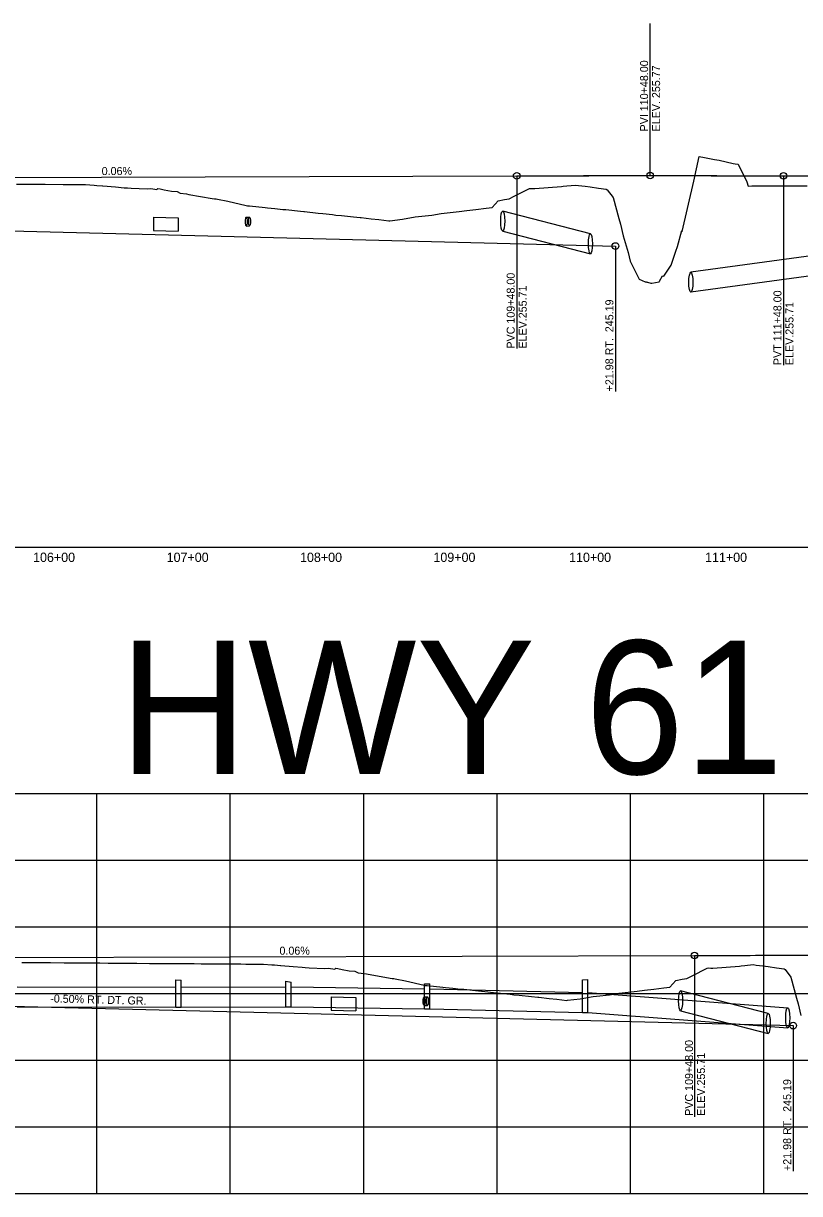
# Model space of a CAD drawing. Extents: x 1930770 to 1938778, y 596900 to 600561.
# Drawn here: x 1932838 to 1933419, y 598575 to 599452 of the extents above; entities that cross this region are included whole.
import ezdxf

# ---------------------------------------------------------------- set-up
doc = ezdxf.new("R2010")
doc.units = 0
for name, color, linetype in [('R_Concrete Hidden', 7, 'Continuous'), ('S_CROSS_DRAIN_ANNOT', 7, 'Continuous'), ('S_DROP_INLET_ANNOT', 7, 'Continuous'), ('S_ELECTRIC_UTILITIES_ANNOT', 7, 'Continuous'), ('S_HIST_HIGH_WATER_ANNOT', 7, 'Continuous'), ('S_SIGN_ANNOT', 7, 'Continuous'), ('S_STORM_SEWER_ANNOT', 7, 'Continuous'), ('S_UTILITY_POLE_ANNOT', 7, 'Continuous'), ('S_WATER_UTILITIES_ANNOT', 7, 'Continuous')]:
    doc.layers.add(name, color=color, linetype=linetype)

msp = doc.modelspace()

# ---------------------------------------------------------------- linework, layer by layer
at = {"layer": 'R_Concrete Hidden'}
for p, q in [((1933262.65, 599294.36), (1933196.9, 599311.36)), ((1932935.08, 599306.74), (1932953.5, 599306.36)), ((1932935.08, 599306.74), (1932935.08, 599296.74)), ((1932953.5, 599306.36), (1932953.5, 599296.36)), ((1933004.67, 599306.81), (1933007.12, 599306.86)), ((1933004.67, 599300.15), (1933007.12, 599300.2)), ((1932935.08, 599296.74), (1932953.5, 599296.36)), ((1933196.9, 599296.36), (1933262.65, 599279.36)), ((1933539.31, 599292.76), (1933337.92, 599265.46)), ((1933539.31, 599277.76), (1933337.92, 599250.46)), ((1933068.38, 598722.08), (1933086.8, 598721.7)), ((1933068.38, 598722.08), (1933068.38, 598712.08)), ((1933086.8, 598721.7), (1933086.8, 598711.7)), ((1933137.97, 598722.15), (1933140.42, 598722.2)), ((1933395.95, 598709.7), (1933330.2, 598726.7)), ((1933068.38, 598712.08), (1933086.8, 598711.7)), ((1933137.97, 598715.49), (1933140.42, 598715.54)), ((1933330.2, 598711.7), (1933395.95, 598694.7))]:
    msp.add_line(p, q, dxfattribs=at)
for centre, major_axis in [((1933196.9, 599303.86), (0, 7.5)), ((1933004.67, 599303.48), (0, 3.33)), ((1933007.12, 599303.53), (0, 3.33)), ((1933262.65, 599286.86), (0, 7.5)), ((1933337.92, 599257.96), (0, 7.5)), ((1933137.97, 598718.82), (0, 3.33)), ((1933140.42, 598718.87), (0, 3.33)), ((1933330.2, 598719.2), (0, 7.5)), ((1933395.95, 598702.2), (0, 7.5))]:
    msp.add_ellipse(centre, major_axis=major_axis, ratio=0.2, dxfattribs=at)
at = {"layer": 'S_CROSS_DRAIN_ANNOT'}
for p, q in [((1932159.37, 599059.21), (1933659.37, 599059.21)), ((1932092.67, 598574.55), (1934792.67, 598574.55))]:
    msp.add_line(p, q, dxfattribs=at)
at = {"layer": 'S_ELECTRIC_UTILITIES_ANNOT'}
for p, q in [((1933307.37, 599368.08), (1933307.37, 599452.08)), ((1933307.37, 599338.08), (1933307.37, 599368.08)), ((1933207.37, 599337.78), (1933207.37, 599307.78)), ((1933257.37, 599337.93), (1933307.37, 599338.08)), ((1933307.37, 599338.08), (1933357.37, 599337.93)), ((1933407.37, 599337.78), (1933407.37, 599307.78)), ((1933207.37, 599307.78), (1933207.37, 599208.23)), ((1933407.37, 599307.78), (1933407.37, 599195.87)), ((1933281.35, 599285.15), (1933281.35, 599260.15)), ((1933281.35, 599260.15), (1933281.35, 599176.15)), ((1933340.67, 598753.12), (1933340.67, 598723.12)), ((1933390.67, 598753.27), (1933440.67, 598753.42)), ((1933340.67, 598723.12), (1933340.67, 598632.18)), ((1933414.65, 598700.49), (1933414.65, 598675.49)), ((1933414.65, 598675.49), (1933414.65, 598591.49))]:
    msp.add_line(p, q, dxfattribs=at)
for centre in [(1933207.37, 599337.78), (1933307.37, 599338.08), (1933407.37, 599337.78), (1933340.67, 598753.12)]:
    msp.add_circle(centre, 2.5, dxfattribs=at)
at = {"layer": 'S_HIST_HIGH_WATER_ANNOT'}
for p, q in [((1932609.37, 599335.99), (1933207.37, 599337.78)), ((1933407.37, 599337.78), (1933559.37, 599337.33)), ((1932250.92, 599310.91), (1933281.35, 599285.15)), ((1932742.67, 598751.33), (1933340.67, 598753.12)), ((1932384.22, 598726.25), (1933414.65, 598700.49))]:
    msp.add_line(p, q, dxfattribs=at)
for points in [[(1933207.37, 599337.78), (1933211.54, 599337.79), (1933215.71, 599337.81), (1933219.87, 599337.82), (1933224.04, 599337.83), (1933228.21, 599337.84), (1933232.37, 599337.85), (1933236.54, 599337.86), (1933240.71, 599337.87), (1933244.87, 599337.87), (1933249.04, 599337.88), (1933253.21, 599337.89), (1933257.37, 599337.89), (1933261.54, 599337.9), (1933265.71, 599337.91), (1933269.87, 599337.91), (1933274.04, 599337.92), (1933278.21, 599337.92), (1933282.37, 599337.92), (1933286.54, 599337.93), (1933290.71, 599337.93), (1933294.87, 599337.93), (1933299.04, 599337.93), (1933303.21, 599337.93), (1933311.54, 599337.93), (1933315.71, 599337.93), (1933319.87, 599337.93), (1933324.04, 599337.93), (1933328.21, 599337.93), (1933332.37, 599337.92), (1933336.54, 599337.92), (1933340.71, 599337.92), (1933344.87, 599337.91), (1933349.04, 599337.91), (1933353.21, 599337.9), (1933357.37, 599337.89), (1933361.54, 599337.89), (1933365.71, 599337.88), (1933369.87, 599337.87), (1933374.04, 599337.87), (1933378.21, 599337.86), (1933382.37, 599337.85), (1933386.54, 599337.84), (1933390.71, 599337.83), (1933394.87, 599337.82), (1933399.04, 599337.81), (1933403.21, 599337.79), (1933407.37, 599337.78)], [(1933340.67, 598753.12), (1933344.83, 598753.14), (1933349, 598753.15), (1933353.17, 598753.16), (1933357.33, 598753.17), (1933361.5, 598753.18), (1933365.67, 598753.19), (1933369.83, 598753.2), (1933374, 598753.21), (1933378.17, 598753.21), (1933382.33, 598753.22), (1933386.5, 598753.23), (1933390.67, 598753.24), (1933394.83, 598753.24), (1933399, 598753.25), (1933403.17, 598753.25), (1933407.33, 598753.26), (1933411.5, 598753.26), (1933415.67, 598753.26), (1933419.83, 598753.27)]]:
    msp.add_lwpolyline(points, dxfattribs=at)
for centre in [(1933281.35, 599285.15), (1933414.65, 598700.49)]:
    msp.add_circle(centre, 2.5, dxfattribs=at)
at = {"layer": 'S_SIGN_ANNOT'}
for p, q in [((1932832.98, 598729.7), (1932951.83, 598729.25)), ((1932951.83, 598714.25), (1932951.83, 598734.86)), ((1932951.83, 598734.86), (1932955.83, 598734.68)), ((1932955.83, 598714.25), (1932955.83, 598734.68)), ((1932955.83, 598729.25), (1933034.38, 598729.5)), ((1933034.38, 598714.5), (1933034.38, 598733.98)), ((1933034.38, 598733.98), (1933038.38, 598733.01)), ((1933038.38, 598714.5), (1933038.38, 598733.01)), ((1933038.38, 598729.5), (1933138.28, 598728.15)), ((1933138.28, 598731.79), (1933142.28, 598731.83)), ((1933138.28, 598713.15), (1933138.28, 598731.79)), ((1933142.28, 598713.15), (1933142.28, 598731.83)), ((1933256.79, 598734.85), (1933260.79, 598735.16)), ((1933256.79, 598710.35), (1933256.79, 598734.85)), ((1933260.79, 598710.35), (1933260.79, 598735.16)), ((1933142.28, 598728.15), (1933256.79, 598725.35)), ((1933260.79, 598725.35), (1933410.55, 598713.9)), ((1932832.98, 598714.7), (1932951.83, 598714.25)), ((1932951.83, 598714.25), (1932955.83, 598714.25)), ((1932955.83, 598714.25), (1933034.38, 598714.5)), ((1933034.38, 598714.5), (1933038.38, 598714.5)), ((1933038.38, 598714.5), (1933138.28, 598713.15)), ((1933138.28, 598713.15), (1933142.28, 598713.15)), ((1933142.28, 598713.15), (1933256.79, 598710.35)), ((1933256.79, 598710.35), (1933260.79, 598710.35)), ((1933260.79, 598710.35), (1933410.55, 598698.9))]:
    msp.add_line(p, q, dxfattribs=at)
msp.add_ellipse((1933410.55, 598706.4), major_axis=(0, 7.5), ratio=0.2, dxfattribs=at)
at = {"layer": 'S_UTILITY_POLE_ANNOT'}
for p, q in [((1932092.67, 598874.55), (1934792.67, 598874.55)), ((1932092.67, 598874.55), (1934792.67, 598874.55)), ((1932892.67, 598574.55), (1932892.67, 598874.55)), ((1932992.67, 598574.55), (1932992.67, 598874.55)), ((1933092.67, 598574.55), (1933092.67, 598874.55)), ((1933192.67, 598574.55), (1933192.67, 598874.55)), ((1933292.67, 598574.55), (1933292.67, 598874.55)), ((1933392.67, 598574.55), (1933392.67, 598874.55)), ((1932092.67, 598824.55), (1934792.67, 598824.55)), ((1932092.67, 598774.55), (1934792.67, 598774.55)), ((1932092.67, 598724.55), (1934792.67, 598724.55)), ((1932092.67, 598674.55), (1934792.67, 598674.55)), ((1932092.67, 598624.55), (1934792.67, 598624.55))]:
    msp.add_line(p, q, dxfattribs=at)
at = {"layer": 'S_WATER_UTILITIES_ANNOT'}
for points in [[(1932832.33, 599331.63), (1932837.63, 599331.6), (1932847.24, 599331.56), (1932853.87, 599331.51), (1932867.33, 599331.39), (1932871.01, 599331.37), (1932875.4, 599331.35), (1932884.15, 599331.3), (1932890.63, 599330.8), (1932892.57, 599330.64), (1932896.93, 599330.28), (1932897.21, 599330.26), (1932906.49, 599329.49), (1932913.18, 599328.9), (1932915.58, 599328.67), (1932918.47, 599328.53), (1932930.25, 599327.93), (1932933.05, 599328.19), (1932937.67, 599327.53), (1932938.46, 599328.33), (1932940, 599328), (1932943.12, 599327.32), (1932948.47, 599326.23), (1932952.81, 599326.05), (1932955.2, 599324.86), (1932959.73, 599324.21), (1932961.54, 599323.9), (1932979.09, 599320.87), (1932980.8, 599320.61), (1932982.02, 599320.42), (1932983.07, 599320.23), (1932990.81, 599318.82), (1933004.6, 599315.59), (1933005.47, 599315.38), (1933006.99, 599315.26), (1933018.76, 599314.01), (1933020.67, 599313.86), (1933026.14, 599313.29), (1933032.05, 599312.63), (1933034.4, 599312.43), (1933045.33, 599311.23), (1933047.67, 599311.04), (1933048.18, 599310.99), (1933058.6, 599309.79), (1933062.05, 599309.5), (1933069.2, 599308.69), (1933071.87, 599308.37), (1933075.97, 599308), (1933085.13, 599306.92), (1933089.96, 599306.5), (1933090.74, 599306.41), (1933098.37, 599305.48), (1933104.06, 599304.98), (1933111.6, 599304.07), (1933112.27, 599304.15), (1933121.68, 599305.22), (1933131.32, 599306.94), (1933133.81, 599307.22), (1933143.72, 599308.31), (1933150.68, 599309.43), (1933155.34, 599309.95), (1933164.34, 599310.94), (1933169.88, 599311.79), (1933176.77, 599312.55), (1933184.36, 599313.42), (1933188.97, 599314.12), (1933193.48, 599319.13), (1933198.19, 599319.98), (1933201.6, 599320.59), (1933205.59, 599322.51), (1933216.99, 599328.32), (1933217.84, 599328.4), (1933219.62, 599328.33), (1933221.07, 599328.27), (1933241.04, 599329.88), (1933242.26, 599329.98), (1933245.04, 599330.16), (1933251.38, 599330.89), (1933253.59, 599330.41), (1933258.67, 599330.02), (1933262.47, 599329.48), (1933268.8, 599328.59), (1933274.52, 599327.81), (1933275.22, 599327.29), (1933279.67, 599321.45), (1933283.9, 599305.89), (1933285.1, 599301.48), (1933287.2, 599292.69), (1933290.84, 599280.19), (1933292.49, 599273.87), (1933297.52, 599263.68), (1933299.12, 599260.21), (1933303.8, 599258.41), (1933304.45, 599258.24), (1933304.97, 599258.1), (1933305.32, 599258.02), (1933308.01, 599257.34), (1933308.7, 599257.24), (1933314.06, 599258.22), (1933314.33, 599258.89), (1933316.7, 599262.87), (1933317.7, 599262.63), (1933323.18, 599270.71), (1933326.75, 599281.33), (1933327.94, 599284.86), (1933331.25, 599296.76), (1933331.36, 599296.14), (1933340.14, 599333.74), (1933344.26, 599352.39), (1933348.18, 599351.54), (1933355.63, 599349.91), (1933359.08, 599349.51), (1933369.6, 599347.12), (1933371.19, 599346.76), (1933373.5, 599346.49), (1933379.91, 599333.39), (1933380.9, 599329.96), (1933383.59, 599330.21), (1933391.03, 599330.27), (1933401.85, 599330.36), (1933404.38, 599330.38), (1933412.46, 599330.35), (1933425.19, 599330.29)], [(1932836.43, 598747.8), (1932852.83, 598747.78), (1932857.17, 598747.8), (1932857.96, 598747.79), (1932868.1, 598747.71), (1932869.7, 598747.7), (1932879.49, 598747.62), (1932881.22, 598747.61), (1932882.23, 598747.6), (1932894.35, 598747.51), (1932894.75, 598747.5), (1932901.03, 598747.46), (1932902.89, 598747.44), (1932907.25, 598747.39), (1932908.37, 598747.39), (1932922.56, 598747.27), (1932932.04, 598747.19), (1932940.15, 598747.16), (1932944.1, 598747.13), (1932956.85, 598747.04), (1932965.63, 598746.98), (1932970.93, 598746.94), (1932980.53, 598746.9), (1932987.16, 598746.85), (1933000.63, 598746.73), (1933004.3, 598746.72), (1933008.7, 598746.69), (1933017.44, 598746.65), (1933023.92, 598746.14), (1933025.86, 598745.98), (1933030.23, 598745.62), (1933030.51, 598745.6), (1933039.79, 598744.83), (1933046.47, 598744.24), (1933048.87, 598744.01), (1933051.76, 598743.87), (1933063.54, 598743.27), (1933066.35, 598743.53), (1933070.97, 598742.87), (1933071.76, 598743.67), (1933073.3, 598743.34), (1933076.42, 598742.66), (1933081.76, 598741.57), (1933086.1, 598741.39), (1933088.5, 598740.2), (1933093.03, 598739.55), (1933094.83, 598739.24), (1933112.39, 598736.21), (1933114.09, 598735.95), (1933115.31, 598735.76), (1933116.37, 598735.57), (1933124.11, 598734.16), (1933137.9, 598730.93), (1933138.76, 598730.72), (1933140.28, 598730.6), (1933152.06, 598729.35), (1933153.96, 598729.2), (1933159.43, 598728.63), (1933165.34, 598727.97), (1933167.7, 598727.78), (1933178.62, 598726.57), (1933180.97, 598726.38), (1933181.48, 598726.33), (1933191.9, 598725.13), (1933195.34, 598724.84), (1933202.5, 598724.03), (1933205.17, 598723.71), (1933209.27, 598723.34), (1933218.42, 598722.26), (1933223.26, 598721.84), (1933224.03, 598721.75), (1933231.67, 598720.82), (1933237.36, 598720.32), (1933244.9, 598719.41), (1933245.57, 598719.49), (1933254.98, 598720.56), (1933264.62, 598722.28), (1933267.1, 598722.56), (1933277.01, 598723.65), (1933283.98, 598724.78), (1933288.63, 598725.29), (1933297.63, 598726.28), (1933303.17, 598727.13), (1933310.06, 598727.89), (1933317.66, 598728.76), (1933322.27, 598729.46), (1933326.77, 598734.48), (1933331.49, 598735.32), (1933334.89, 598735.93), (1933338.88, 598737.85), (1933350.28, 598743.66), (1933351.14, 598743.74), (1933352.91, 598743.67), (1933354.36, 598743.62), (1933374.34, 598745.22), (1933375.56, 598745.32), (1933378.34, 598745.5), (1933384.67, 598746.23), (1933386.88, 598745.75), (1933391.97, 598745.36), (1933395.77, 598744.82), (1933402.09, 598743.93), (1933407.81, 598743.15), (1933408.51, 598742.63), (1933412.96, 598736.79), (1933417.19, 598721.23), (1933418.39, 598716.82), (1933420.5, 598708.03)]]:
    msp.add_lwpolyline(points, dxfattribs=at)

# ---------------------------------------------------------------- texts
at = {"layer": 'S_DROP_INLET_ANNOT'}
for s, p in [('106+00', (1932844.8, 599048.21)), ('107+00', (1932944.94, 599048.21)), ('108+00', (1933044.94, 599048.21)), ('109+00', (1933144.94, 599048.21)), ('110+00', (1933246.64, 599048.21)), ('111+00', (1933348.58, 599048.21))]:
    msp.add_text(s, height=7, dxfattribs=at).set_placement(p)
at = {"layer": 'S_ELECTRIC_UTILITIES_ANNOT'}
for s, rotation, p in [('PVI 110+48.00', 90, (1933305.87, 599371.08)), ('ELEV. 255.77', 90, (1933314.87, 599371.08)), ('0.06%', 0.17189, (1932896.25, 599338.35)), ('PVC 109+48.00', 90, (1933205.87, 599208.23)), ('ELEV.255.71', 90, (1933214.87, 599208.23)), ('PVT 111+48.00', 90, (1933405.87, 599195.87)), ('+21.98 RT.  245.19', 90, (1933279.85, 599176.15)), ('ELEV.255.71', 90, (1933414.87, 599195.87)), ('0.06%', 0.17189, (1933029.54, 598753.69)), ('-0.50% RT. DT. GR.', 358.5679, (1932857.62, 598717.92)), ('PVC 109+48.00', 90, (1933339.54, 598632.86)), ('ELEV.255.71', 90, (1933348.54, 598632.86)), ('+21.98 RT.  245.19', 90, (1933413.15, 598591.49))]:
    msp.add_text(s, height=6, rotation=rotation, dxfattribs=at).set_placement(p)
at = {"layer": 'S_STORM_SEWER_ANNOT'}
msp.add_text('HWY 61', height=100, dxfattribs=at).set_placement((1932909.37, 598889.21))

doc.saveas('drawing.dxf')
